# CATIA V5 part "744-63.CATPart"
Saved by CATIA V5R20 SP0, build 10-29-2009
Part number: 744-63
Revision: TUTTO
Definition: NON CONOSCIUTO
Nomenclature: 744-63
Source: Unknown
Bounding box of the stored display mesh (mm): x -47.5 to 47.5, y -48 to 47.5, z -60 to 56
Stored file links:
  C:\Users\Utente\Desktop\IO LAVORO\3D X SITO CF\X SITO\744\744-63.CATPart
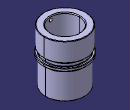
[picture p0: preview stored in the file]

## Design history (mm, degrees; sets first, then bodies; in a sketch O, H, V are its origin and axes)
Body1 "744-63 sol1" (main body)
  Solid1: solid without history
Body2 "IDV1M8_Ingrassatore-1"
  Solid2: solid without history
